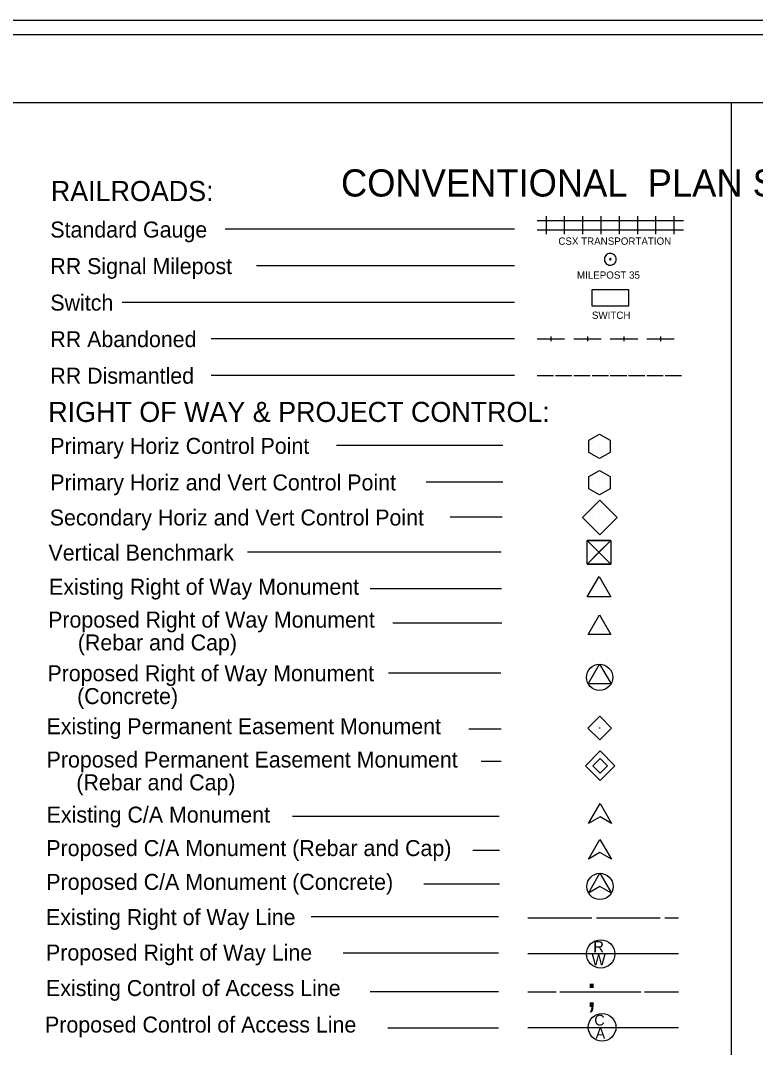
# Model space of a CAD drawing. Extents: x 811137 to 813186, y 647386 to 648494.
# Drawn here: x 811598 to 812004, y 647927 to 648494 of the extents above; entities that cross this region are included whole.
import ezdxf

# ---------------------------------------------------------------- set-up
doc = ezdxf.new("R2010")
doc.units = 0
for name, color, linetype in [('Default', 7, 'Continuous'), ('P_RDY_ROW_Permanent_Easement', 7, 'Continuous'), ('Sheet_Plan', 7, 'Continuous'), ('Sheet_Symbology', 7, 'Continuous'), ('z - Construction', 7, 'Continuous')]:
    doc.layers.add(name, color=color, linetype=linetype)

msp = doc.modelspace()

# ---------------------------------------------------------------- linework, layer by layer
at = {"layer": 'Default'}
msp.add_lwpolyline([(812820.63, 648494.02), (811136.63, 648494.02), (811136.63, 647394.02), (812820.63, 647394.02)], close=True, dxfattribs=at)
at = {"layer": 'P_RDY_ROW_Permanent_Easement'}
msp.add_line((811918.26, 648082.48), (811918.26, 648082.48), dxfattribs=at)
for points in [[(811918.26, 648090.6), (811926.38, 648082.48), (811918.26, 648074.35), (811910.13, 648082.48)], [(811918.26, 648086.54), (811922.32, 648082.48), (811918.26, 648078.41), (811914.2, 648082.48)]]:
    msp.add_lwpolyline(points, close=True, dxfattribs=at)
at = {"layer": 'Sheet_Plan'}
msp.add_line((812803.27, 648448.58), (811178.27, 648448.58), dxfattribs=at)
at = {"layer": 'Sheet_Symbology'}
for p, q in [((811883.55, 648383.54), (811893.64, 648383.54)), ((811888.6, 648375.97), (811888.6, 648386.06)), ((811893.64, 648383.54), (811903.73, 648383.54)), ((811898.69, 648375.97), (811898.69, 648386.06)), ((811903.73, 648383.54), (811913.82, 648383.54)), ((811908.78, 648375.97), (811908.78, 648386.06)), ((811913.82, 648383.54), (811923.91, 648383.54)), ((811918.87, 648375.97), (811918.87, 648386.06)), ((811923.91, 648383.54), (811934, 648383.54)), ((811928.96, 648375.97), (811928.96, 648386.06)), ((811934, 648383.54), (811944.09, 648383.54)), ((811939.04, 648375.97), (811939.04, 648386.06)), ((811944.09, 648383.54), (811954.18, 648383.54)), ((811949.13, 648375.97), (811949.13, 648386.06)), ((811954.18, 648383.54), (811964.27, 648383.54)), ((811959.22, 648375.97), (811959.22, 648386.06)), ((811871.05, 648378.73), (811711.22, 648378.73)), ((811883.55, 648378.49), (811893.64, 648378.49)), ((811893.64, 648378.49), (811903.73, 648378.49)), ((811903.73, 648378.49), (811913.82, 648378.49)), ((811913.82, 648378.49), (811923.91, 648378.49)), ((811923.91, 648378.49), (811934, 648378.49)), ((811934, 648378.49), (811944.09, 648378.49)), ((811944.09, 648378.49), (811954.18, 648378.49)), ((811954.18, 648378.49), (811964.27, 648378.49)), ((811871.05, 648358.56), (811728.51, 648358.56)), ((811871.05, 648338.38), (811654.22, 648338.38)), ((811871.05, 648318.2), (811703.4, 648318.2)), ((811883.55, 648318.2), (811898.69, 648318.2)), ((811891.12, 648319.46), (811891.12, 648316.94)), ((811903.73, 648318.2), (811918.87, 648318.2)), ((811911.3, 648319.46), (811911.3, 648316.94)), ((811923.91, 648318.2), (811939.04, 648318.2)), ((811931.48, 648319.46), (811931.48, 648316.94)), ((811944.09, 648318.2), (811959.22, 648318.2)), ((811951.66, 648319.46), (811951.66, 648316.94)), ((811871.05, 648298.02), (811703.4, 648298.02)), ((811871.05, 648298.02), (811703.4, 648298.02)), ((811883.55, 648298.02), (811892.63, 648298.02)), ((811893.64, 648298.02), (811902.72, 648298.02)), ((811903.73, 648298.02), (811912.81, 648298.02)), ((811913.82, 648298.02), (811922.9, 648298.02)), ((811923.91, 648298.02), (811932.99, 648298.02)), ((811934, 648298.02), (811943.08, 648298.02)), ((811944.09, 648298.02), (811953.17, 648298.02)), ((811954.18, 648298.02), (811963.26, 648298.02)), ((811864.58, 648259.28), (811772.74, 648259.28)), ((811917.99, 648258.91), (811917.99, 648258.91)), ((811864.58, 648239.1), (811822.29, 648239.1)), ((811917.98, 648238.76), (811917.98, 648238.76)), ((811864.27, 648219.73), (811835.46, 648219.73)), ((811918.12, 648219.52), (811918.12, 648219.52)), ((811863.57, 648200.34), (811723.49, 648200.34)), ((811917.61, 648200.35), (811917.61, 648200.35)), ((811863.89, 648180.18), (811791.19, 648180.18)), ((811863.99, 648161.22), (811803.72, 648161.22)), ((811917.98, 648158.58), (811917.98, 648158.58)), ((811863.48, 648133.57), (811801.45, 648133.57)), ((811918, 648131.28), (811918, 648131.28)), ((811863.56, 648102.61), (811845.85, 648102.61)), ((811918.08, 648103.27), (811918.08, 648103.27)), ((811863.56, 648084.83), (811852.66, 648084.83)), ((811911.93, 648050.62), (811918.24, 648061.52)), ((811918.24, 648061.52), (811924.55, 648050.62)), ((811862.56, 648054.34), (811748.31, 648054.34)), ((811918.24, 648054.25), (811911.93, 648050.62)), ((811924.55, 648050.62), (811918.24, 648054.25)), ((811911.9, 648030.83), (811918.21, 648041.73)), ((811918.21, 648041.73), (811924.51, 648030.83)), ((811862.66, 648035.64), (811847.96, 648035.64)), ((811918.21, 648034.46), (811911.9, 648030.83)), ((811924.51, 648030.83), (811918.21, 648034.46)), ((811911.9, 648012.16), (811918.21, 648023.06)), ((811918.21, 648023.06), (811924.51, 648012.16)), ((811862.66, 648016.97), (811820.89, 648016.97)), ((811918.21, 648015.79), (811911.9, 648012.16)), ((811924.51, 648012.16), (811918.21, 648015.79)), ((811862.22, 647999.03), (811758.78, 647999.03)), ((811878.39, 647998.45), (811913.7, 647998.45)), ((811916.22, 647998.45), (811951.54, 647998.45)), ((811954.06, 647998.45), (811961.63, 647998.45)), ((811862.22, 647978.85), (811776.41, 647978.85)), ((811878.39, 647978.73), (811961.63, 647978.73)), ((811862.22, 647957.54), (811791.35, 647957.54)), ((811878.39, 647957.54), (811893.99, 647957.54)), ((811896.01, 647957.54), (811940.82, 647957.54)), ((811942.84, 647957.54), (811961.63, 647957.54)), ((811862.22, 647937.54), (811800.96, 647937.54)), ((811878.39, 647937.93), (811961.63, 647937.93))]:
    msp.add_line(p, q, dxfattribs=at)
for points in [[(811927.2, 648362.15), (811927.13, 648362.8), (811926.94, 648363.46), (811926.61, 648364.05), (811926.15, 648364.51), (811925.63, 648364.9), (811925.04, 648365.23), (811924.45, 648365.36), (811923.73, 648365.42), (811923.07, 648365.29), (811922.48, 648365.1), (811921.89, 648364.77), (811921.43, 648364.31), (811921.04, 648363.72), (811920.78, 648363.13), (811920.65, 648362.47), (811920.65, 648361.82), (811920.78, 648361.16), (811921.04, 648360.57), (811921.43, 648359.98), (811921.89, 648359.53), (811922.48, 648359.2), (811923.07, 648359), (811923.73, 648358.87), (811924.45, 648358.93), (811925.04, 648359.07), (811925.63, 648359.39), (811926.15, 648359.79), (811926.61, 648360.25), (811926.94, 648360.84), (811927.13, 648361.49), (811927.2, 648362.15)], [(811924.06, 648362.54), (811923.86, 648362.54), (811923.66, 648362.41), (811923.53, 648362.21), (811923.6, 648362.02), (811923.73, 648361.82), (811923.92, 648361.75), (811924.12, 648361.82), (811924.25, 648361.95), (811924.32, 648362.21), (811924.25, 648362.41), (811924.06, 648362.54)], [(811917.99, 648252.2), (811912.14, 648255.52), (811912.14, 648262.23), (811917.99, 648265.62), (811923.84, 648262.3), (811923.84, 648255.52), (811917.99, 648252.2)], [(811924.14, 648206.88), (811911.06, 648193.79), (811917.6, 648200.34), (811924.14, 648193.79), (811911.06, 648206.88)], [(811917.6, 648200.34), (811924.14, 648206.88), (811911.06, 648206.88), (811917.6, 648200.34)], [(811917.6, 648200.34), (811911.06, 648193.79), (811924.14, 648193.79), (811917.6, 648200.34)], [(811911.16, 648175.68), (811917.71, 648187.06), (811924.27, 648175.68), (811911.16, 648175.68)]]:
    msp.add_lwpolyline(points, dxfattribs=at)
for points in [[(811913.82, 648345.4), (811934, 648345.4), (811934, 648336.22), (811913.82, 648336.22)], [(811912.1, 648242.17), (811918.01, 648245.47), (811923.93, 648242.22), (811923.84, 648235.43), (811917.92, 648232), (811912.1, 648235.3)], [(811908.62, 648219.55), (811918.16, 648229.09), (811927.72, 648219.53), (811918.18, 648209.99)], [(811911.06, 648206.88), (811924.14, 648206.88), (811924.14, 648193.79), (811911.06, 648193.79)], [(811911.68, 648154.95), (811917.98, 648165.85), (811924.29, 648154.95)], [(811911.69, 648127.65), (811918, 648138.55), (811924.31, 648127.65)], [(811911.53, 648103.27), (811918.08, 648109.82), (811924.63, 648103.27), (811918.08, 648096.71)]]:
    msp.add_lwpolyline(points, close=True, dxfattribs=at)
for centre, radius in [((811918, 648131.28), 7.26), ((811918.08, 648103.27), 0.127), ((811918.21, 648015.79), 7.26), ((811918.6, 647978.52), 7.82), ((811919.4, 647938.03), 7.65)]:
    msp.add_circle(centre, radius, dxfattribs=at)
at = {"layer": 'z - Construction'}
for p, q in [((812840.77, 648486.08), (811140.78, 648486.08)), ((811990.77, 648448.58), (811990.75, 647423.58))]:
    msp.add_line(p, q, dxfattribs=at)

# ---------------------------------------------------------------- texts
at = {"layer": 'Sheet_Symbology'}
for s, height, p in [('CONVENTIONAL  PLAN SHEET SYMBOLS', 15, (811775.17, 648396.83)), ('RAILROADS:', 11.098, (811614.89, 648394.32)), ('Standard Gauge', 8.8282, (811614.62, 648374.17)), ('RR Signal Milepost', 8.8282, (811614.62, 648353.99)), ('Switch', 8.828, (811614.62, 648333.81)), ('RR Abandoned', 8.8282, (811614.62, 648313.63)), ('RR Dismantled', 8.8282, (811614.62, 648293.45)), ('RIGHT OF WAY & PROJECT CONTROL:', 11.0983, (811613.47, 648272.33)), ('Primary Horiz Control Point', 8.8282, (811614.62, 648254.69)), ('Primary Horiz and Vert Control Point', 8.8282, (811614.62, 648234.51)), ('Secondary Horiz and Vert Control Point', 8.8282, (811614.3, 648215.14)), ('Vertical Benchmark', 8.8282, (811613.61, 648195.75)), ('Existing Right of Way Monument', 8.8282, (811613.92, 648176.87)), ('Proposed Right of Way Monument', 8.8282, (811613.4, 648158.73)), ('     (Rebar and Cap)', 8.8282, (811613.4, 648146.12)), ('Proposed Right of Way Monument', 8.8282, (811613.02, 648129.12)), ('     (Concrete)', 8.8282, (811613.02, 648116.51)), ('Existing Permanent Easement Monument', 8.8282, (811612.53, 648099.87)), ('Proposed Permanent Easement Monument', 8.8282, (811612.57, 648081.47)), ('     (Rebar and Cap)', 8.8282, (811612.57, 648068.86)), ('Existing C/A Monument', 8.8282, (811612.6, 648051.03)), ('Proposed C/A Monument (Rebar and Cap)', 8.8282, (811612.39, 648032.56)), ('Proposed C/A Monument (Concrete)', 8.8282, (811612.39, 648013.89)), ('Existing Right of Way Line', 8.8282, (811612.25, 647994.44)), ('Proposed Right of Way Line', 8.8282, (811612.25, 647974.89)), ('R', 6.13, (811914.5, 647979.44)), ('W', 6.13, (811913.62, 647972.22)), ('Existing Control of Access Line', 8.8282, (811612.25, 647955.26)), (';', 16.65, (811910.47, 647949.28)), ('Proposed Control of Access Line', 8.8282, (811611.7, 647935.09)), ('C', 5.99, (811915.07, 647938.94)), ('A', 5.99, (811915.79, 647931.74))]:
    msp.add_text(s, height=height, dxfattribs=at).set_placement(p)
for s, height, p in [('CSX TRANSPORTATION', 4.0357, (811895.22, 648370.18)), ('MILEPOST 35', 4.0357, (811905.5, 648351.44)), ('SWITCH', 4.036, (811913.77, 648329.25))]:
    msp.add_text(s, height=height, rotation=360, dxfattribs=at).set_placement(p)

doc.saveas('drawing.dxf')
